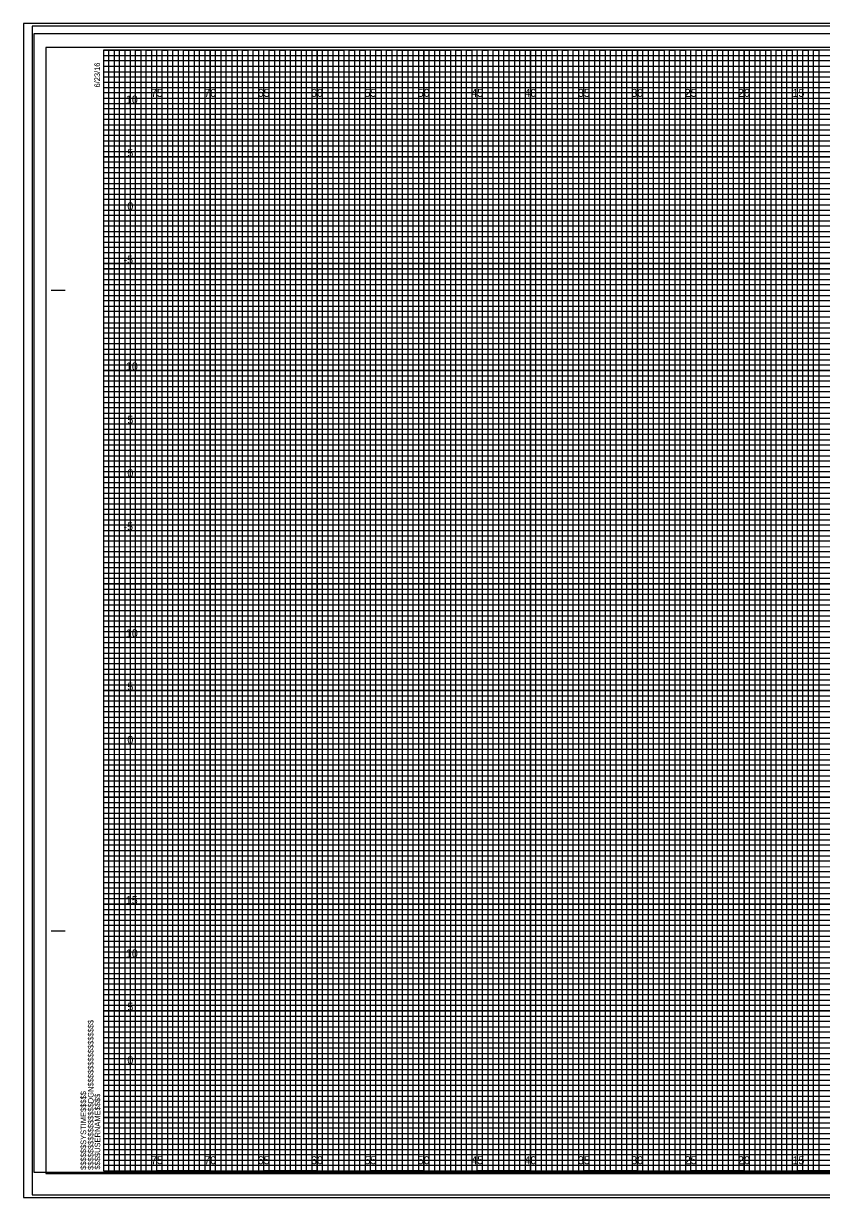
# Model space of a CAD drawing. Extents: x -8 to 162, y 108 to 218.
# Drawn here: x -7.5 to 67.2, y 107.5 to 217.5 of the extents above; entities that cross this region are included whole.
import ezdxf

# ---------------------------------------------------------------- set-up
doc = ezdxf.new("R2010")
doc.units = 0
for name, color, linetype in [('Prop XS Elevation Labels', 7, 'Continuous'), ('Prop XS Offset Labels', 7, 'Continuous'), ('Sheet Cross Section CELL', 7, 'Continuous'), ('Sheet Cross Section Grid Major CELL', 7, 'Continuous'), ('Sheet Cross Section Grid Middle CELL', 7, 'Continuous'), ('Sheet Cross Section Grid Minor 1 CELL', 7, 'Continuous'), ('Sheet Cross Section Grid Minor 2 CELL', 7, 'Continuous'), ('Sheet Cutting Line CELL', 7, 'Continuous'), ('Sheet DOT Grid CELL', 7, 'Continuous'), ('Sheet Plot Border Inside CELL', 7, 'Continuous'), ('Sheet Plot Border Outside CELL', 7, 'Continuous'), ('Stewart Plot Border DJ1055', 7, 'Continuous'), ('Stewart Plot Border DJ1055 Invisible', 7, 'Continuous'), ('Stewart Plot Border Xerox6279 and LJ5000', 7, 'Continuous')]:
    doc.layers.add(name, color=color, linetype=linetype)

msp = doc.modelspace()

# ---------------------------------------------------------------- linework, layer by layer
at = {"layer": 'Sheet Cross Section CELL'}
for p, q in [((-4.9, 192.5), (-3.65, 192.5)), ((-4.85, 192.5), (-3.6, 192.5)), ((-4.9, 132.5), (-3.65, 132.5)), ((-4.85, 132.5), (-3.6, 132.5)), ((0, 110), (0, 110)), ((0, 110), (0, 110)), ((0, 110), (0, 110)), ((0, 110), (0, 110)), ((0, 110), (0, 110)), ((0, 110), (0, 110)), ((0, 110), (0, 110))]:
    msp.add_line(p, q, dxfattribs=at)
msp.add_lwpolyline([(160, 215), (0, 215), (0, 110), (160, 110)], close=True, dxfattribs=at)
at = {"layer": 'Sheet Cross Section Grid Major CELL'}
for p, q in [((5, 215), (0, 215)), ((5, 110), (5, 215)), ((15, 215), (10, 215)), ((10, 215), (10, 110)), ((15, 110), (15, 215)), ((25, 215), (20, 215)), ((20, 215), (20, 110)), ((25, 110), (25, 215)), ((35, 215), (30, 215)), ((30, 215), (30, 110)), ((35, 110), (35, 215)), ((45, 215), (40, 215)), ((40, 215), (40, 110)), ((45, 110), (45, 215)), ((55, 215), (50, 215)), ((50, 215), (50, 110)), ((55, 110), (55, 215)), ((65, 215), (60, 215)), ((60, 215), (60, 110)), ((65, 110), (65, 215)), ((10, 110), (5, 110)), ((20, 110), (15, 110)), ((30, 110), (25, 110)), ((40, 110), (35, 110)), ((50, 110), (45, 110)), ((60, 110), (55, 110)), ((70, 110), (65, 110))]:
    msp.add_line(p, q, dxfattribs=at)
for points in [[(0, 210), (160, 210), (160, 205), (0, 205)], [(0, 200), (160, 200), (160, 195), (0, 195)], [(0, 190), (160, 190), (160, 185), (0, 185)], [(0, 180), (160, 180), (160, 175), (0, 175)], [(0, 170), (160, 170), (160, 165), (0, 165)], [(0, 160), (160, 160), (160, 155), (0, 155)], [(0, 150), (160, 150), (160, 145), (0, 145)], [(0, 140), (160, 140), (160, 135), (0, 135)], [(0, 130), (160, 130), (160, 125), (0, 125)], [(0, 120), (160, 120), (160, 115), (0, 115)]]:
    msp.add_lwpolyline(points, dxfattribs=at)
at = {"layer": 'Sheet Cross Section Grid Middle CELL'}
for points in [[(0, 215), (2.5, 215), (2.5, 110), (7.5, 110), (7.5, 215), (12.5, 215), (12.5, 110), (17.5, 110), (17.5, 215), (22.5, 215), (22.5, 110), (27.5, 110), (27.5, 215), (32.5, 215), (32.5, 110), (37.5, 110), (37.5, 215), (42.5, 215), (42.5, 110), (47.5, 110), (47.5, 215), (52.5, 215), (52.5, 110), (57.5, 110), (57.5, 215), (62.5, 215), (62.5, 110), (67.5, 110)], [(0, 212.5), (137.5, 212.5)], [(0, 202.5), (160, 202.5), (160, 207.5), (0, 207.5)], [(0, 192.5), (160, 192.5), (160, 197.5), (0, 197.5)], [(0, 182.5), (160, 182.5), (160, 187.5), (0, 187.5)], [(0, 172.5), (160, 172.5), (160, 177.5), (0, 177.5)], [(0, 162.5), (160, 162.5), (160, 167.5), (0, 167.5)], [(0, 152.5), (160, 152.5), (160, 157.5), (0, 157.5)], [(0, 142.5), (160, 142.5), (160, 147.5), (0, 147.5)], [(0, 132.5), (160, 132.5), (160, 137.5), (0, 137.5)], [(0, 122.5), (160, 122.5), (160, 127.5), (0, 127.5)], [(0, 112.5), (160, 112.5), (160, 117.5), (0, 117.5)]]:
    msp.add_lwpolyline(points, dxfattribs=at)
at = {"layer": 'Sheet Cross Section Grid Minor 1 CELL'}
for p, q in [((0, 214.5), (130, 214.5)), ((130, 213.99), (0, 213.99)), ((0, 213.99), (0, 213.5)), ((0, 213.5), (130, 213.5)), ((130, 212.94), (0, 212.94)), ((0, 212.94), (0, 212)), ((0, 212), (160, 212))]:
    msp.add_line(p, q, dxfattribs=at)
for points in [[(0, 211.5), (135, 211.5), (160, 211.5), (160, 211), (0, 211)], [(0, 210.5), (160, 210.5), (160, 209.5), (0, 209.5)], [(0, 209), (160, 209), (160, 208.5), (0, 208.49)], [(0, 208), (160, 208), (160, 207), (0, 207)], [(0, 206.5), (160, 206.5), (160, 206), (0, 206)], [(0, 205.5), (160, 205.5), (160, 204.5), (0, 204.5)], [(0, 204), (160, 204), (160, 203.5), (0, 203.5)], [(0, 203), (160, 203), (160, 202), (0, 202)], [(0, 201.5), (160, 201.5), (160, 201), (0, 201)], [(0, 200.5), (160, 200.5), (160, 199.5), (0, 199.5)], [(0, 199), (160, 199), (160, 198.5), (0, 198.5)], [(0, 198), (160, 198), (160, 196.97), (160, 196.5), (160, 196), (0, 196)], [(0, 197), (160, 197), (160, 196.5), (0, 196.5)], [(0, 195.5), (160, 195.5), (160, 194.5), (0, 194.52)], [(0, 194.52), (160, 194.5), (160, 194), (0, 194)], [(0, 193.5), (160, 193.5), (160, 193), (0, 193)], [(0, 192), (160, 192), (160, 191.5), (0, 191.5)], [(0, 191), (160, 191), (160, 190.5), (0, 190.5)], [(-0.04, 189.44), (160, 189.44), (160, 188.94), (-0.04, 188.94)], [(0, 188.5), (160, 188.5), (160, 188), (0, 188)], [(0, 187), (160, 187), (160, 186.5), (0, 186.5)], [(0, 186), (160, 186), (160, 185.5), (0, 185.5)], [(0, 184.5), (160, 184.5), (160, 184), (0, 184)], [(0, 183.5), (160, 183.5), (160, 183), (0, 183)], [(0, 182), (160, 182), (160, 181.5), (0, 181.5)], [(0, 181), (160, 181), (160, 180.5), (0, 180.5)], [(0, 179.5), (160, 179.5), (160, 178.99), (0, 179)], [(0, 178.5), (160, 178.5), (160, 178), (0, 178)], [(0, 177), (160, 177), (160, 176.5), (0, 176.5)], [(0, 176), (160, 176), (160, 175.5), (0, 175.5)], [(0, 174.5), (160, 174.5), (160, 174), (0, 174)], [(0, 173.5), (160, 173.5), (160, 173), (0, 173)], [(0, 172), (160, 172), (160, 171.5), (0, 171.5)], [(0, 171), (160, 171), (160, 170.5), (0, 170.5)], [(0, 169.5), (160, 169.5), (160, 169), (0, 169)], [(0, 168.5), (160.03, 168.46), (160, 168), (0, 168)], [(0, 167), (160, 167), (160, 166.5), (0, 166.5)], [(0, 166), (160, 166), (160, 165.5), (0, 165.5)], [(0, 164.5), (160, 164.5), (160, 164), (0, 164)], [(0, 163.5), (160, 163.5), (160, 163), (0, 163)], [(0, 162), (160, 162), (160, 161.5), (0, 161.5)], [(0, 161), (160, 161), (160, 160.5), (0, 160.5)], [(0, 159.5), (160, 159.5), (160, 159), (0, 159)], [(0, 158.5), (160, 158.5), (160, 158), (0, 158)], [(0, 157), (160, 157), (160, 156.5), (0, 156.5)], [(0, 156), (160, 156), (160, 155.5), (0, 155.5)], [(0, 154.5), (160, 154.5), (160, 154), (0, 154)], [(0, 153.5), (160, 153.5), (160, 153), (0, 153)], [(0, 152), (160, 152), (160, 151.5), (0, 151.5)], [(0, 151), (160, 151), (160, 150.5), (0, 150.5)], [(0, 149.5), (160, 149.5), (160, 148.99), (0, 149)], [(0, 148.5), (160, 148.5), (160, 148), (0, 148)], [(0, 147), (160, 147), (160, 146.5), (0, 146.5)], [(0, 146), (160, 146), (160, 145.5), (0, 145.5)], [(0, 144.5), (160, 144.5), (160, 144), (0, 144)], [(0, 143.5), (160, 143.5), (160, 143), (0, 143)], [(0, 142), (160, 142), (160, 141.5), (0, 141.5)], [(0, 141), (160, 141), (160, 140.5), (0, 140.5)], [(0, 139.5), (160, 139.5), (160, 139), (0, 139)], [(0, 138.5), (160.03, 138.46), (160, 138), (0, 138)], [(0, 137), (160, 137), (160, 136.5), (0, 136.5)], [(0, 136), (160, 136), (160, 135.5), (0, 135.5)], [(0, 134.5), (160, 134.5), (160, 134), (0, 134)], [(0, 133.5), (160, 133.5), (160, 133), (0, 133)], [(0, 132), (160, 132), (160, 131.5), (0, 131.5)], [(0, 131), (160, 131), (160, 130.5), (0, 130.5)], [(0, 129.5), (160, 129.5), (160, 129), (0, 129)], [(0, 128.5), (160, 128.5), (160, 128), (0, 128)], [(0, 127), (160, 127), (160, 126.5), (0, 126.5)], [(0, 126), (160, 126), (160, 125.5), (0, 125.5)], [(0, 124.5), (160, 124.5), (160, 124), (0, 124)], [(0, 123.5), (160, 123.5), (160, 123), (0, 123)], [(0, 122), (160, 122), (160, 121.5), (0, 121.5)], [(0, 121), (160, 121), (160, 120.5), (0, 120.5)], [(0, 119.5), (160, 119.5), (160, 119), (0, 119)], [(0, 118.5), (160, 118.5), (160, 118), (0, 118)], [(0, 117), (160, 117), (160, 116.5), (0, 116.5)], [(0, 116), (160, 116), (160, 115.5), (0, 115.5)], [(0, 114.5), (160, 114.5), (160, 114), (0, 114)], [(0, 113.5), (160, 113.5), (160, 113), (0, 113)], [(0, 112), (160, 112), (160, 111.5), (0, 111.5)], [(0, 111), (160, 111), (160, 110.5), (0, 110.5)]]:
    msp.add_lwpolyline(points, dxfattribs=at)
at = {"layer": 'Sheet Cross Section Grid Minor 2 CELL'}
for points in [[(0, 110), (0.5, 110), (0.5, 215), (1, 215), (1, 110)], [(1, 110), (1.5, 110), (1.5, 215), (2, 215), (2, 110)], [(2.5, 110), (3, 110), (3, 215), (3.5, 215), (3.5, 110)], [(3.5, 110), (4, 110), (4, 215), (4.5, 215), (4.5, 110)], [(5, 110), (5.5, 110), (5.5, 215), (6, 215), (6, 110)], [(6, 110), (6.5, 110), (6.5, 215), (7, 215), (7, 110)], [(7.5, 110), (8, 110), (8, 215), (8.5, 215), (8.5, 110)], [(8.5, 110), (9, 110), (9, 215), (9.5, 215), (9.5, 110)], [(10, 110), (10.5, 110), (10.5, 215), (11, 215), (11, 110)], [(11, 110), (11.5, 110), (11.5, 215), (12, 215), (12, 110)], [(12.5, 110), (13, 110), (13, 215), (13.5, 215), (13.5, 110)], [(13.5, 110), (14, 110), (14, 215), (14.5, 215), (14.5, 110)], [(15, 110), (15.5, 110), (15.5, 215), (16, 215), (16, 110)], [(16, 110), (16.5, 110), (16.5, 215), (17, 215), (17, 110)], [(17.5, 110), (18, 110), (18, 215), (18.5, 215), (18.5, 110)], [(18.5, 110), (19, 110), (19, 215), (19.5, 215), (19.5, 110)], [(20, 110), (20.5, 110), (20.5, 215), (21, 215), (21, 110)], [(21, 110), (21.5, 110), (21.5, 215), (22, 215), (22, 110)], [(22.5, 110), (23, 110), (23, 215), (23.5, 215), (23.5, 110)], [(23.5, 110), (24, 110), (24, 215), (24.5, 215), (24.5, 110)], [(25, 110), (25.5, 110), (25.5, 215), (26, 215), (26, 110)], [(26, 110), (26.5, 110), (26.5, 215), (27, 215), (27, 110)], [(27.5, 110), (28, 110), (28, 215), (28.5, 215), (28.5, 110)], [(28.5, 110), (29, 110), (29, 215), (29.5, 215), (29.5, 110)], [(30, 110), (30.5, 110), (30.5, 215), (31, 215), (31, 110)], [(31, 110), (31.5, 110), (31.5, 215), (32, 215), (32, 110)], [(32.5, 110), (33, 110), (33, 215), (33.5, 215), (33.5, 110)], [(33.5, 110), (34, 110), (34, 215), (34.5, 215), (34.5, 110)], [(35, 110), (35.5, 110), (35.5, 215), (36, 215), (36, 110)], [(36, 110), (36.5, 110), (36.5, 215), (37, 215), (37, 110)], [(37.5, 110), (38, 110), (38, 215), (38.5, 215), (38.5, 110)], [(38.5, 110), (39, 110), (39, 215), (39.5, 215), (39.5, 110)], [(40, 110), (40.5, 110), (40.5, 215), (41, 215), (41, 110)], [(41, 110), (41.5, 110), (41.5, 215), (42, 215), (42, 110)], [(42.5, 110), (43, 110), (43, 215), (43.5, 215), (43.5, 110)], [(43.5, 110), (44, 110), (44, 215), (44.5, 215), (44.5, 110)], [(45, 110), (45.5, 110), (45.5, 215), (46, 215), (46, 110)], [(46, 110), (46.5, 110), (46.5, 215), (47, 215), (47, 110)], [(47.5, 110), (48, 110), (48, 215), (48.5, 215), (48.5, 110)], [(48.5, 110), (49, 110), (49, 215), (49.5, 215), (49.5, 110)], [(50, 110), (50.5, 110), (50.5, 215), (51, 215), (51, 110)], [(51, 110), (51.5, 110), (51.5, 215), (52, 215), (52, 110)], [(52.5, 110), (53, 110), (53, 215), (53.5, 215), (53.5, 110)], [(53.5, 110), (54, 110), (54, 215), (54.5, 215), (54.5, 110)], [(55, 110), (55.5, 110), (55.5, 215), (56, 215), (56, 110)], [(56, 110), (56.5, 110), (56.5, 215), (57, 215), (57, 110)], [(57.5, 110), (58, 110), (58, 215), (58.5, 215), (58.5, 110)], [(58.5, 110), (59, 110), (59, 215), (59.5, 215), (59.5, 110)], [(60, 110), (60.5, 110), (60.5, 215), (61, 215), (61, 110)], [(61, 110), (61.5, 110), (61.5, 215), (62, 215), (62, 110)], [(62.5, 110), (63, 110), (63, 215), (63.5, 215), (63.5, 110)], [(63.5, 110), (64, 110), (64, 215), (64.5, 215), (64.5, 110)], [(65, 110), (65.5, 110), (65.5, 215), (66, 215), (66, 110)], [(66, 110), (66.5, 110), (66.5, 215), (67, 215), (67, 110)]]:
    msp.add_lwpolyline(points, dxfattribs=at)
at = {"layer": 'Sheet Cutting Line CELL'}
for p, q in [((161.65, 217.25), (-6.7, 217.25)), ((-6.7, 217.25), (-6.7, 107.75)), ((-6.7, 107.75), (161.65, 107.75))]:
    msp.add_line(p, q, dxfattribs=at)
at = {"layer": 'Sheet DOT Grid CELL'}
for p, q in [((5, 110), (5, 215)), ((10, 110), (10, 215)), ((15, 110), (15, 215)), ((20, 110), (20, 215)), ((25, 110), (25, 215)), ((30, 110), (30, 215)), ((35, 110), (35, 215)), ((40, 110), (40, 215)), ((45, 110), (45, 215)), ((50, 110), (50, 215)), ((55, 110), (55, 215)), ((60, 110), (60, 215)), ((65, 110), (65, 215)), ((0, 210), (160, 210)), ((0, 205), (160, 205)), ((0, 200), (160, 200)), ((0, 195), (160, 195)), ((0, 190), (160, 190)), ((0, 185), (160, 185)), ((0, 180), (160, 180)), ((0, 175), (160, 175)), ((0, 170), (160, 170)), ((0, 165), (160, 165)), ((0, 160), (160, 160)), ((0, 155), (160, 155)), ((0, 150), (160, 150)), ((0, 145), (160, 145)), ((0, 140), (160, 140)), ((0, 135), (160, 135)), ((0, 130), (160, 130)), ((0, 125), (160, 125)), ((0, 120), (160, 120)), ((0, 115), (160, 115))]:
    msp.add_line(p, q, dxfattribs=at)
at = {"layer": 'Sheet Plot Border Inside CELL'}
msp.add_lwpolyline([(-5.4, 109.75), (161.2, 109.75), (161.2, 215.25), (-5.4, 215.25)], close=True, dxfattribs=at)
at = {"layer": 'Sheet Plot Border Outside CELL'}
msp.add_lwpolyline([(-6.7, 107.75), (161.65, 107.75), (161.65, 217.25), (-6.7, 217.25)], close=True, dxfattribs=at)
at = {"layer": 'Stewart Plot Border DJ1055'}
msp.add_lwpolyline([(161.52, 216.53), (-6.52, 216.53), (-6.52, 109.87), (161.52, 109.87)], close=True, dxfattribs=at)
at = {"layer": 'Stewart Plot Border DJ1055 Invisible'}
msp.add_lwpolyline([(161.52, 216.53), (-6.52, 216.53), (-6.52, 109.87), (161.52, 109.87)], close=True, dxfattribs=at)
at = {"layer": 'Stewart Plot Border Xerox6279 and LJ5000'}
msp.add_lwpolyline([(-7.5, 107.5), (162.5, 107.5), (162.5, 217.5), (-7.5, 217.5)], close=True, dxfattribs=at)

# ---------------------------------------------------------------- texts
at = {"layer": 'Prop XS Elevation Labels'}
for s, p in [('10', (2.09, 210)), ('5', (2.23, 205)), ('0', (2.23, 200)), ('-5', (1.87, 195)), ('10', (2.09, 185)), ('5', (2.23, 180)), ('0', (2.23, 175)), ('-5', (1.87, 170)), ('10', (2.09, 160)), ('5', (2.23, 155)), ('0', (2.23, 150)), ('15', (2.08, 135)), ('10', (2.09, 130)), ('5', (2.23, 125)), ('0', (2.23, 120))]:
    msp.add_text(s, height=0.75, dxfattribs=at).set_placement(p)
at = {"layer": 'Prop XS Offset Labels'}
for s, p in [('75', (4.44, 210.62)), ('70', (9.43, 210.62)), ('65', (14.44, 210.62)), ('60', (19.43, 210.62)), ('55', (24.44, 210.62)), ('50', (29.43, 210.62)), ('45', (34.44, 210.62)), ('40', (39.43, 210.62)), ('35', (44.44, 210.62)), ('30', (49.43, 210.62)), ('25', (54.44, 210.62)), ('20', (59.43, 210.62)), ('15', (64.53, 210.62)), ('75', (4.44, 110.62)), ('70', (9.43, 110.62)), ('65', (14.44, 110.62)), ('60', (19.43, 110.62)), ('55', (24.44, 110.62)), ('50', (29.43, 110.62)), ('45', (34.44, 110.62)), ('40', (39.43, 110.62)), ('35', (44.44, 110.62)), ('30', (49.43, 110.62)), ('25', (54.44, 110.62)), ('20', (59.43, 110.62)), ('15', (64.53, 110.62))]:
    msp.add_text(s, height=0.75, dxfattribs=at).set_placement(p)
at = {"layer": 'Sheet Cross Section CELL'}
for s, p in [('6/23/16', (-0.33, 211.5)), ('$$$$$$$$$$$$$$$$DGN$$$$$$$$$$$$$$$$', (-0.94, 110.09)), ('$$$$$$SYSTIME$$$$$', (-1.63, 110.09)), ('$$$$USERNAME$$$$', (-0.31, 110.12))]:
    msp.add_text(s, height=0.525, rotation=90, dxfattribs=at).set_placement(p)

doc.saveas('drawing.dxf')
